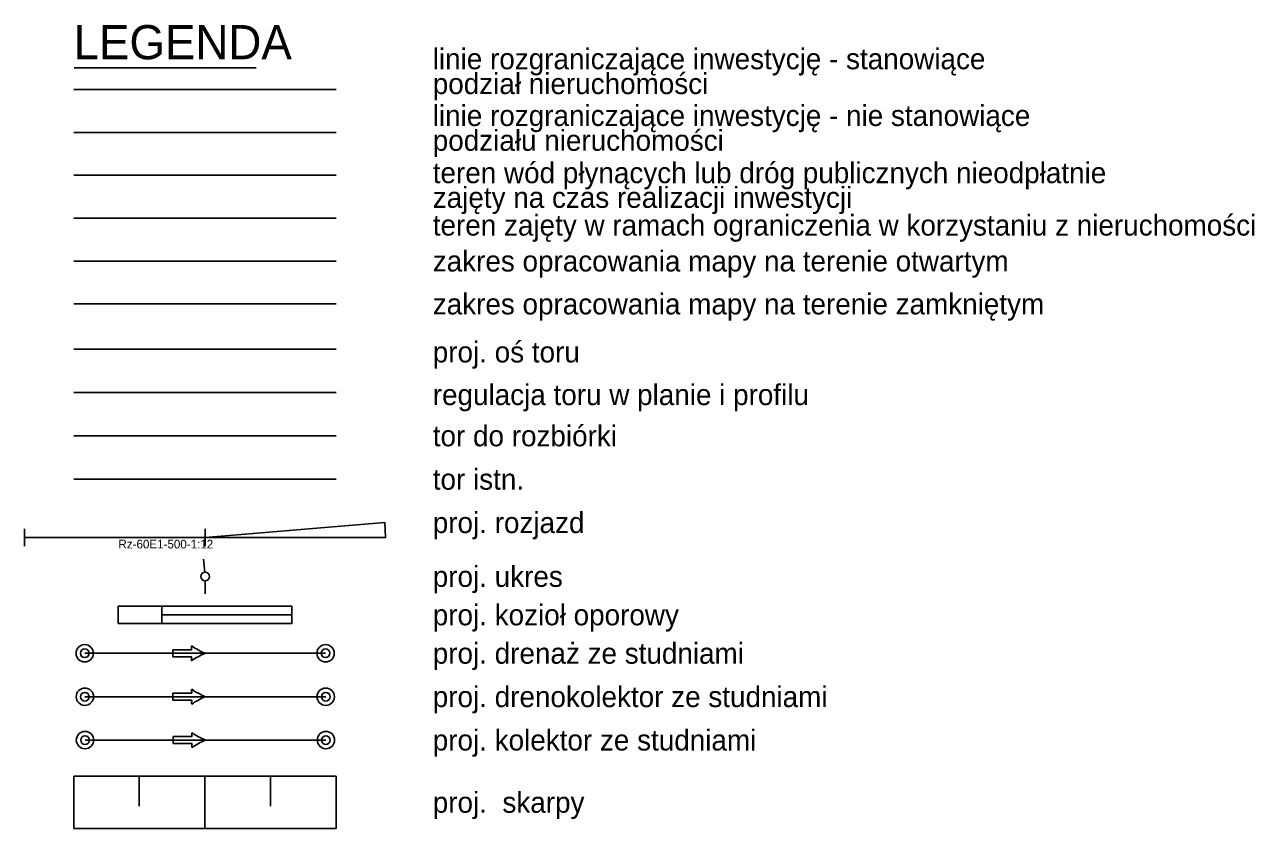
# Model space of a CAD drawing. Extents: x 6559661.1 to 6559724.9, y 5529293.8 to 5529378.1.
# Drawn here: x 6559661.1 to 6559724.9, y 5529336.5 to 5529378.1 of the extents above; entities that cross this region are included whole.
import ezdxf

# ---------------------------------------------------------------- set-up
doc = ezdxf.new("R2010")
doc.units = 0
for name, color, linetype in [('_ZAKRES OPRACOWANIA MAPY NA TERENIE ZAMKNIĘTYM', 7, 'Continuous'), ('_ZAKRES OPRACOWANIA_MAPY NA TERENIE OTWARTYM', 7, 'Continuous'), ('Default', 7, 'Continuous'), ('DLLK obszar inwestycji - wody i drogi publiczne', 7, 'Continuous'), ('linia czasowej zajetosci terenu', 7, 'Continuous'), ('linia rozgraniczajace tory', 7, 'Continuous'), ('linie rozgraniczajace do podzialu lub przejecia w calosci', 7, 'Continuous'), ('TOR_PS_ODW-drenaze', 7, 'Continuous'), ('TOR_PS_ODW-drenokolektory', 7, 'Continuous'), ('TOR_PS_ODW-kolektory', 7, 'Continuous'), ('TOR_PS_ODW-studnie PEHD', 7, 'Continuous'), ('TOR_PS_OPIS_O-opisy rurociagow', 7, 'Continuous'), ('TOR_PS_OPIS_T-opis geometrii-wzdluz_cz torowa', 7, 'Continuous'), ('TOR_PS_OPIS_T-ukresy', 7, 'Continuous'), ('TOR_PS_T-rozjazdy projektowane', 7, 'Continuous'), ('TOR_PS_T-skarpy projektowane', 7, 'Continuous'), ('TOR_PS_T-tory i rozjazdy do rozbiorki', 7, 'Continuous'), ('TOR_PS_T-tory i rozjazdy istniejace', 7, 'Continuous'), ('TOR_PS_T-tory projektowane', 7, 'Continuous'), ('TOR_PS_T-wypelnienia', 7, 'Continuous')]:
    doc.layers.add(name, color=color, linetype=linetype)

# ---------------------------------------------------------------- blocks, each defined once
blk = doc.blocks.new('koziol 15+5')
at = {"layer": 'Default'}
for p, q in [((15, 1), (14.3, 1)), ((15, 1), (15, -1)), ((20, 0), (20, 1)), ((0, 0), (15, 0)), ((15, -1), (14.3, -1))]:
    blk.add_line(p, q, dxfattribs=at)
blk.add_lwpolyline([(20, 1), (0, 1), (0, -1), (20, -1)], close=True, dxfattribs=at)

msp = doc.modelspace()

# ---------------------------------------------------------------- linework, layer by layer
at = {"layer": '_ZAKRES OPRACOWANIA MAPY NA TERENIE ZAMKNIĘTYM'}
msp.add_lwpolyline([(6559677.246, 5529363.65), (6559663.642, 5529363.65)], dxfattribs=at)
at = {"layer": '_ZAKRES OPRACOWANIA_MAPY NA TERENIE OTWARTYM'}
msp.add_line((6559663.642, 5529365.875), (6559677.246, 5529365.875), dxfattribs=at)
at = {"layer": 'Default'}
msp.add_line((6559663.662, 5529375.902), (6559673.102, 5529375.902), dxfattribs=at)
at = {"layer": 'DLLK obszar inwestycji - wody i drogi publiczne'}
msp.add_line((6559677.246, 5529370.325), (6559663.642, 5529370.325), dxfattribs=at)
at = {"layer": 'linia czasowej zajetosci terenu'}
msp.add_line((6559663.642, 5529368.1), (6559677.246, 5529368.1), dxfattribs=at)
at = {"layer": 'linia rozgraniczajace tory'}
msp.add_lwpolyline([(6559677.246, 5529374.775), (6559663.642, 5529374.775)], dxfattribs=at)
at = {"layer": 'linie rozgraniczajace do podzialu lub przejecia w calosci'}
msp.add_lwpolyline([(6559663.642, 5529372.55), (6559677.246, 5529372.55)], dxfattribs=at)
at = {"layer": 'TOR_PS_ODW-drenaze'}
msp.add_line((6559664.215, 5529345.538), (6559676.705, 5529345.538), dxfattribs=at)
at = {"layer": 'TOR_PS_ODW-drenokolektory'}
msp.add_line((6559664.222, 5529343.288), (6559676.713, 5529343.288), dxfattribs=at)
at = {"layer": 'TOR_PS_ODW-kolektory'}
msp.add_line((6559664.23, 5529341.038), (6559676.72, 5529341.038), dxfattribs=at)
at = {"layer": 'TOR_PS_ODW-studnie PEHD'}
for centre, radius in [((6559664.215, 5529345.538), 0.45), ((6559676.705, 5529345.538), 0.45), ((6559664.215, 5529345.538), 0.225), ((6559676.705, 5529345.538), 0.225), ((6559664.222, 5529343.288), 0.45), ((6559664.222, 5529343.288), 0.225), ((6559676.713, 5529343.288), 0.45), ((6559676.713, 5529343.288), 0.225), ((6559664.23, 5529341.038), 0.45), ((6559676.72, 5529341.038), 0.45), ((6559664.23, 5529341.038), 0.225), ((6559676.72, 5529341.038), 0.225)]:
    msp.add_circle(centre, radius, dxfattribs=at)
at = {"layer": 'TOR_PS_OPIS_O-opisy rurociagow'}
for p, q in [((6559669.766, 5529345.718), (6559668.782, 5529345.718)), ((6559668.782, 5529345.718), (6559668.782, 5529345.358)), ((6559668.782, 5529345.718), (6559668.782, 5529345.358)), ((6559669.766, 5529345.718), (6559668.782, 5529345.718)), ((6559668.782, 5529345.358), (6559669.766, 5529345.358)), ((6559669.766, 5529345.358), (6559668.782, 5529345.358)), ((6559669.773, 5529343.468), (6559668.79, 5529343.468)), ((6559668.79, 5529343.468), (6559668.79, 5529343.108)), ((6559668.79, 5529343.468), (6559668.79, 5529343.108)), ((6559669.773, 5529343.468), (6559668.79, 5529343.468)), ((6559668.79, 5529343.108), (6559669.773, 5529343.108)), ((6559669.773, 5529343.108), (6559668.79, 5529343.108)), ((6559669.781, 5529341.218), (6559668.797, 5529341.218)), ((6559668.797, 5529341.218), (6559668.797, 5529340.858)), ((6559668.797, 5529341.218), (6559668.797, 5529340.858)), ((6559669.781, 5529341.218), (6559668.797, 5529341.218)), ((6559668.797, 5529340.858), (6559669.781, 5529340.858)), ((6559669.781, 5529340.858), (6559668.797, 5529340.858))]:
    msp.add_line(p, q, dxfattribs=at)
for points in [[(6559669.756, 5529345.921), (6559669.756, 5529345.921)], [(6559669.756, 5529345.156), (6559669.756, 5529345.156)], [(6559669.764, 5529343.671), (6559669.764, 5529343.671)], [(6559669.764, 5529342.906), (6559669.764, 5529342.906)], [(6559669.771, 5529341.421), (6559669.771, 5529341.421)], [(6559669.771, 5529340.656), (6559669.771, 5529340.656)]]:
    msp.add_lwpolyline(points, dxfattribs=at)
for centre, radius, start, end in [((6559670.16, 5529345.838), 0.412, 168.40471, 196.86595), ((6559670.16, 5529345.838), 0.412, 168.40471, 196.86595), ((6559672.213, 5529349.602), 4.426, 236.29015, 246.67198), ((6559672.213, 5529349.602), 4.426, 236.29015, 246.67198), ((6559670.16, 5529345.239), 0.412, 163.13406, 191.5953), ((6559670.16, 5529345.239), 0.412, 163.13406, 191.5953), ((6559672.213, 5529341.474), 4.426, 113.32804, 123.70986), ((6559672.213, 5529341.474), 4.426, 113.32804, 123.70986), ((6559670.167, 5529343.588), 0.412, 168.40471, 196.86595), ((6559670.167, 5529343.588), 0.412, 168.40471, 196.86595), ((6559672.22, 5529347.352), 4.426, 236.29015, 246.67198), ((6559672.22, 5529347.352), 4.426, 236.29015, 246.67198), ((6559670.167, 5529342.989), 0.412, 163.13406, 191.5953), ((6559670.167, 5529342.989), 0.412, 163.13406, 191.5953), ((6559672.22, 5529339.224), 4.426, 113.32804, 123.70986), ((6559672.22, 5529339.224), 4.426, 113.32804, 123.70986), ((6559670.175, 5529341.338), 0.412, 168.40471, 196.86595), ((6559670.175, 5529341.338), 0.412, 168.40471, 196.86595), ((6559670.175, 5529340.739), 0.412, 163.13406, 191.5953), ((6559670.175, 5529340.739), 0.412, 163.13406, 191.5953), ((6559672.228, 5529345.102), 4.426, 236.29015, 246.67198), ((6559672.228, 5529345.102), 4.426, 236.29015, 246.67198), ((6559672.228, 5529336.974), 4.426, 113.32804, 123.70986), ((6559672.228, 5529336.974), 4.426, 113.32804, 123.70986)]:
    msp.add_arc(centre, radius, start, end, dxfattribs=at)
at = {"layer": 'TOR_PS_OPIS_T-ukresy'}
for p, q in [((6559670.437, 5529349.746), (6559670.381, 5529350.423)), ((6559670.456, 5529349.297), (6559670.456, 5529348.617))]:
    msp.add_line(p, q, dxfattribs=at)
msp.add_circle((6559670.456, 5529349.522), 0.225, dxfattribs=at)
at = {"layer": 'TOR_PS_T-rozjazdy projektowane'}
for p, q in [((6559661.097, 5529351.085), (6559661.097, 5529351.985)), ((6559670.456, 5529351.085), (6559670.456, 5529351.985))]:
    msp.add_line(p, q, dxfattribs=at)
msp.add_lwpolyline([(6559661.097, 5529351.535), (6559670.456, 5529351.535), (6559679.815, 5529351.535), (6559679.783, 5529352.312), (6559670.456, 5529351.535)], dxfattribs=at)
at = {"layer": 'TOR_PS_T-skarpy projektowane'}
for p, q in [((6559663.642, 5529339.159), (6559677.246, 5529339.159)), ((6559663.642, 5529339.159), (6559663.642, 5529336.459)), ((6559667.043, 5529339.159), (6559667.043, 5529337.607)), ((6559670.444, 5529339.159), (6559670.444, 5529336.459)), ((6559673.845, 5529339.159), (6559673.845, 5529337.607)), ((6559677.246, 5529339.159), (6559677.246, 5529336.459)), ((6559663.642, 5529336.459), (6559677.246, 5529336.459))]:
    msp.add_line(p, q, dxfattribs=at)
at = {"layer": 'TOR_PS_T-tory i rozjazdy do rozbiorki'}
msp.add_line((6559663.642, 5529356.812), (6559677.246, 5529356.812), dxfattribs=at)
at = {"layer": 'TOR_PS_T-tory i rozjazdy istniejace'}
msp.add_line((6559663.642, 5529354.562), (6559677.246, 5529354.562), dxfattribs=at)
at = {"layer": 'TOR_PS_T-tory projektowane'}
for p, q in [((6559663.642, 5529361.312), (6559677.246, 5529361.312)), ((6559663.642, 5529359.062), (6559677.246, 5529359.062))]:
    msp.add_line(p, q, dxfattribs=at)
at = {"layer": 'TOR_PS_T-wypelnienia'}
msp.add_line((6559679.815, 5529351.535), (6559670.456, 5529351.535), dxfattribs=at)
msp.add_lwpolyline([(6559670.456, 5529351.535), (6559679.783, 5529352.312), (6559679.815, 5529351.535)], dxfattribs=at)

# ---------------------------------------------------------------- block references
at = {"layer": 'TOR_PS_T-tory projektowane', "xscale": 0.45000000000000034, "yscale": 0.4500000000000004, "rotation": -179.99999999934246}
msp.add_blockref('koziol 15+5', (6559674.956, 5529347.53), dxfattribs=at)

# ---------------------------------------------------------------- texts
at = {"layer": 'Default'}
msp.add_text('LEGENDA', height=1.7707, rotation=360, dxfattribs=at).set_placement((6559663.638, 5529376.34))
at = {"layer": 'TOR_PS_ODW-drenaze'}
msp.add_text('proj. drenaż ze studniami', height=1.08, rotation=360, dxfattribs=at).set_placement((6559682.263, 5529344.998))
at = {"layer": 'TOR_PS_ODW-drenokolektory'}
msp.add_text('proj. drenokolektor ze studniami', height=1.08, rotation=360, dxfattribs=at).set_placement((6559682.263, 5529342.748))
at = {"layer": 'TOR_PS_ODW-kolektory'}
msp.add_text('proj. kolektor ze studniami', height=1.08, rotation=360, dxfattribs=at).set_placement((6559682.263, 5529340.498))
at = {"layer": 'TOR_PS_OPIS_T-opis geometrii-wzdluz_cz torowa'}
msp.add_text('Rz-60E1-500-1:12', height=0.45, rotation=360, dxfattribs=at).set_placement((6559665.963, 5529350.975))
at = {"layer": 'TOR_PS_T-skarpy projektowane'}
msp.add_text('proj.  skarpy', height=1.08, rotation=360, dxfattribs=at).set_placement((6559682.263, 5529337.269))
at = {"layer": 'TOR_PS_T-tory i rozjazdy do rozbiorki'}
msp.add_text('tor do rozbiórki', height=1.08, rotation=360, dxfattribs=at).set_placement((6559682.263, 5529356.272))
at = {"layer": 'TOR_PS_T-tory i rozjazdy istniejace'}
for s, p in [('tor istn.', (6559682.263, 5529354.022)), ('proj. rozjazd', (6559682.263, 5529351.772)), ('proj. ukres', (6559682.263, 5529348.982)), ('proj. kozioł oporowy', (6559682.263, 5529346.99))]:
    msp.add_text(s, height=1.08, rotation=360, dxfattribs=at).set_placement(p)
at = {"layer": 'TOR_PS_T-tory projektowane'}
for s, p in [('linie rozgraniczające inwestycję - stanowiące', (6559682.263, 5529375.822)), ('podział nieruchomości', (6559682.263, 5529374.534)), ('linie rozgraniczające inwestycję - nie stanowiące', (6559682.263, 5529372.88)), ('podziału nieruchomości', (6559682.263, 5529371.593)), ('teren wód płynących lub dróg publicznych nieodpłatnie', (6559682.263, 5529369.914)), ('zajęty na czas realizacji inwestycji', (6559682.263, 5529368.635)), ('teren zajęty w ramach ograniczenia w korzystaniu z nieruchomości', (6559682.263, 5529367.197)), ('zakres opracowania mapy na terenie otwartym', (6559682.263, 5529365.335)), ('zakres opracowania mapy na terenie zamkniętym', (6559682.263, 5529363.11)), ('proj. oś toru', (6559682.263, 5529360.62)), ('regulacja toru w planie i profilu', (6559682.263, 5529358.407))]:
    msp.add_text(s, height=1.08, rotation=360, dxfattribs=at).set_placement(p)

doc.saveas('drawing.dxf')
